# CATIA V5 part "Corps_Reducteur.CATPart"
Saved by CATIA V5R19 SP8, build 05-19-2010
Part number: Corps_réducteur
Revision: ANY
Definition: UNKNOWN
Nomenclature: 1
Source: Unknown
Bounding box of the stored display mesh (mm): x 0 to 23, y -23 to 34, z -55.5 to 6
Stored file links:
  D:\Documents\1_Travail\2- 2I2D\1 - Cours et TD\2- TD\3-TD Assemblage\Pompe AirMan\Corps_Reducteur.CATPart
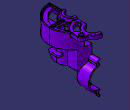
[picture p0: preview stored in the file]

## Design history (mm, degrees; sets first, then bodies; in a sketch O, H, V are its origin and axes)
Body1 "Enlèv. mat.-Extru.6" (main body)
  Solid1: solid without history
